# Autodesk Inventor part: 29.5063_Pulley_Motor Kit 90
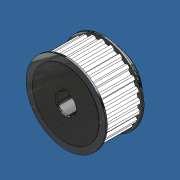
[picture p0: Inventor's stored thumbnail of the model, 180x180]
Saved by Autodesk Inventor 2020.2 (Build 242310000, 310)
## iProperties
Created: 2016-11
Part Number: 29.5063_Pulley_Motor Kit 90
Material: Aluminum 6061
Document SubType Name: Modeling
Designer: Mike Taylor
Mass: 517.165 g
Surface Area: 292.204 cm^2
Volume: 191.543 cm^3
Density: 2.7 g/cm^3
Appearance: Aluminum - Flat
Translation Standard: STEP AP214IS
FileName: E:\MT_Pool\Minitec_Framing\29-5063-0FZ.000 _Riemenscheibe bearbeitet.stp
PreProcessor: Autodesk Inventor 2016
PostProcessor: Build: 160, Release: 2012 RTM - Date: Tue 03/01/2011
Sent Units: millimeter
Uncertainty: 0.01
Author: Mike Taylor
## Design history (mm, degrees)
node "000227571"
sketch "Sketch1"
  geometry: C1 r 41 at (0, 0) reference; C2 r 34.3 at (0, 0); A1 r 11 centre (0, 0) between (-3, 10.583) and (3, 10.583) reference
  constraints: 1 centre point, 1 coincident
  dimensions: "d0" = 6.7 radial gap between concentric circles of C2 C1
extrude "Extrusion1" cut sketch "Sketch1" distance "d1" = 0.25; taper "d2" = 0 deg
sketch "Sketch2"
  geometry: C1 r 41 at (0, 0) reference; C2 r 34.3 at (0, 0) reference; C3 r 34.3 at (0, 0)
  constraints: 1 centre point, 1 coincident
  dimensions: "d3" = 6.7 radial gap between concentric circles of C3 C1
extrude "Extrusion2" cut sketch "Sketch2" distance "d4" = 0.25; taper "d5" = 0 deg
node "Volumenkörper1"
node "Base1"
